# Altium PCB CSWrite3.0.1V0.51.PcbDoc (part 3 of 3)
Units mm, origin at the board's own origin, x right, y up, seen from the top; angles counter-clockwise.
Board outline 100 x 80 mm, 4 copper layers (Top Layer, power, gnd, Bottom Layer), stack 0.778 mm thick; 246 components, 181 nets, 873 pads, 864 vias.
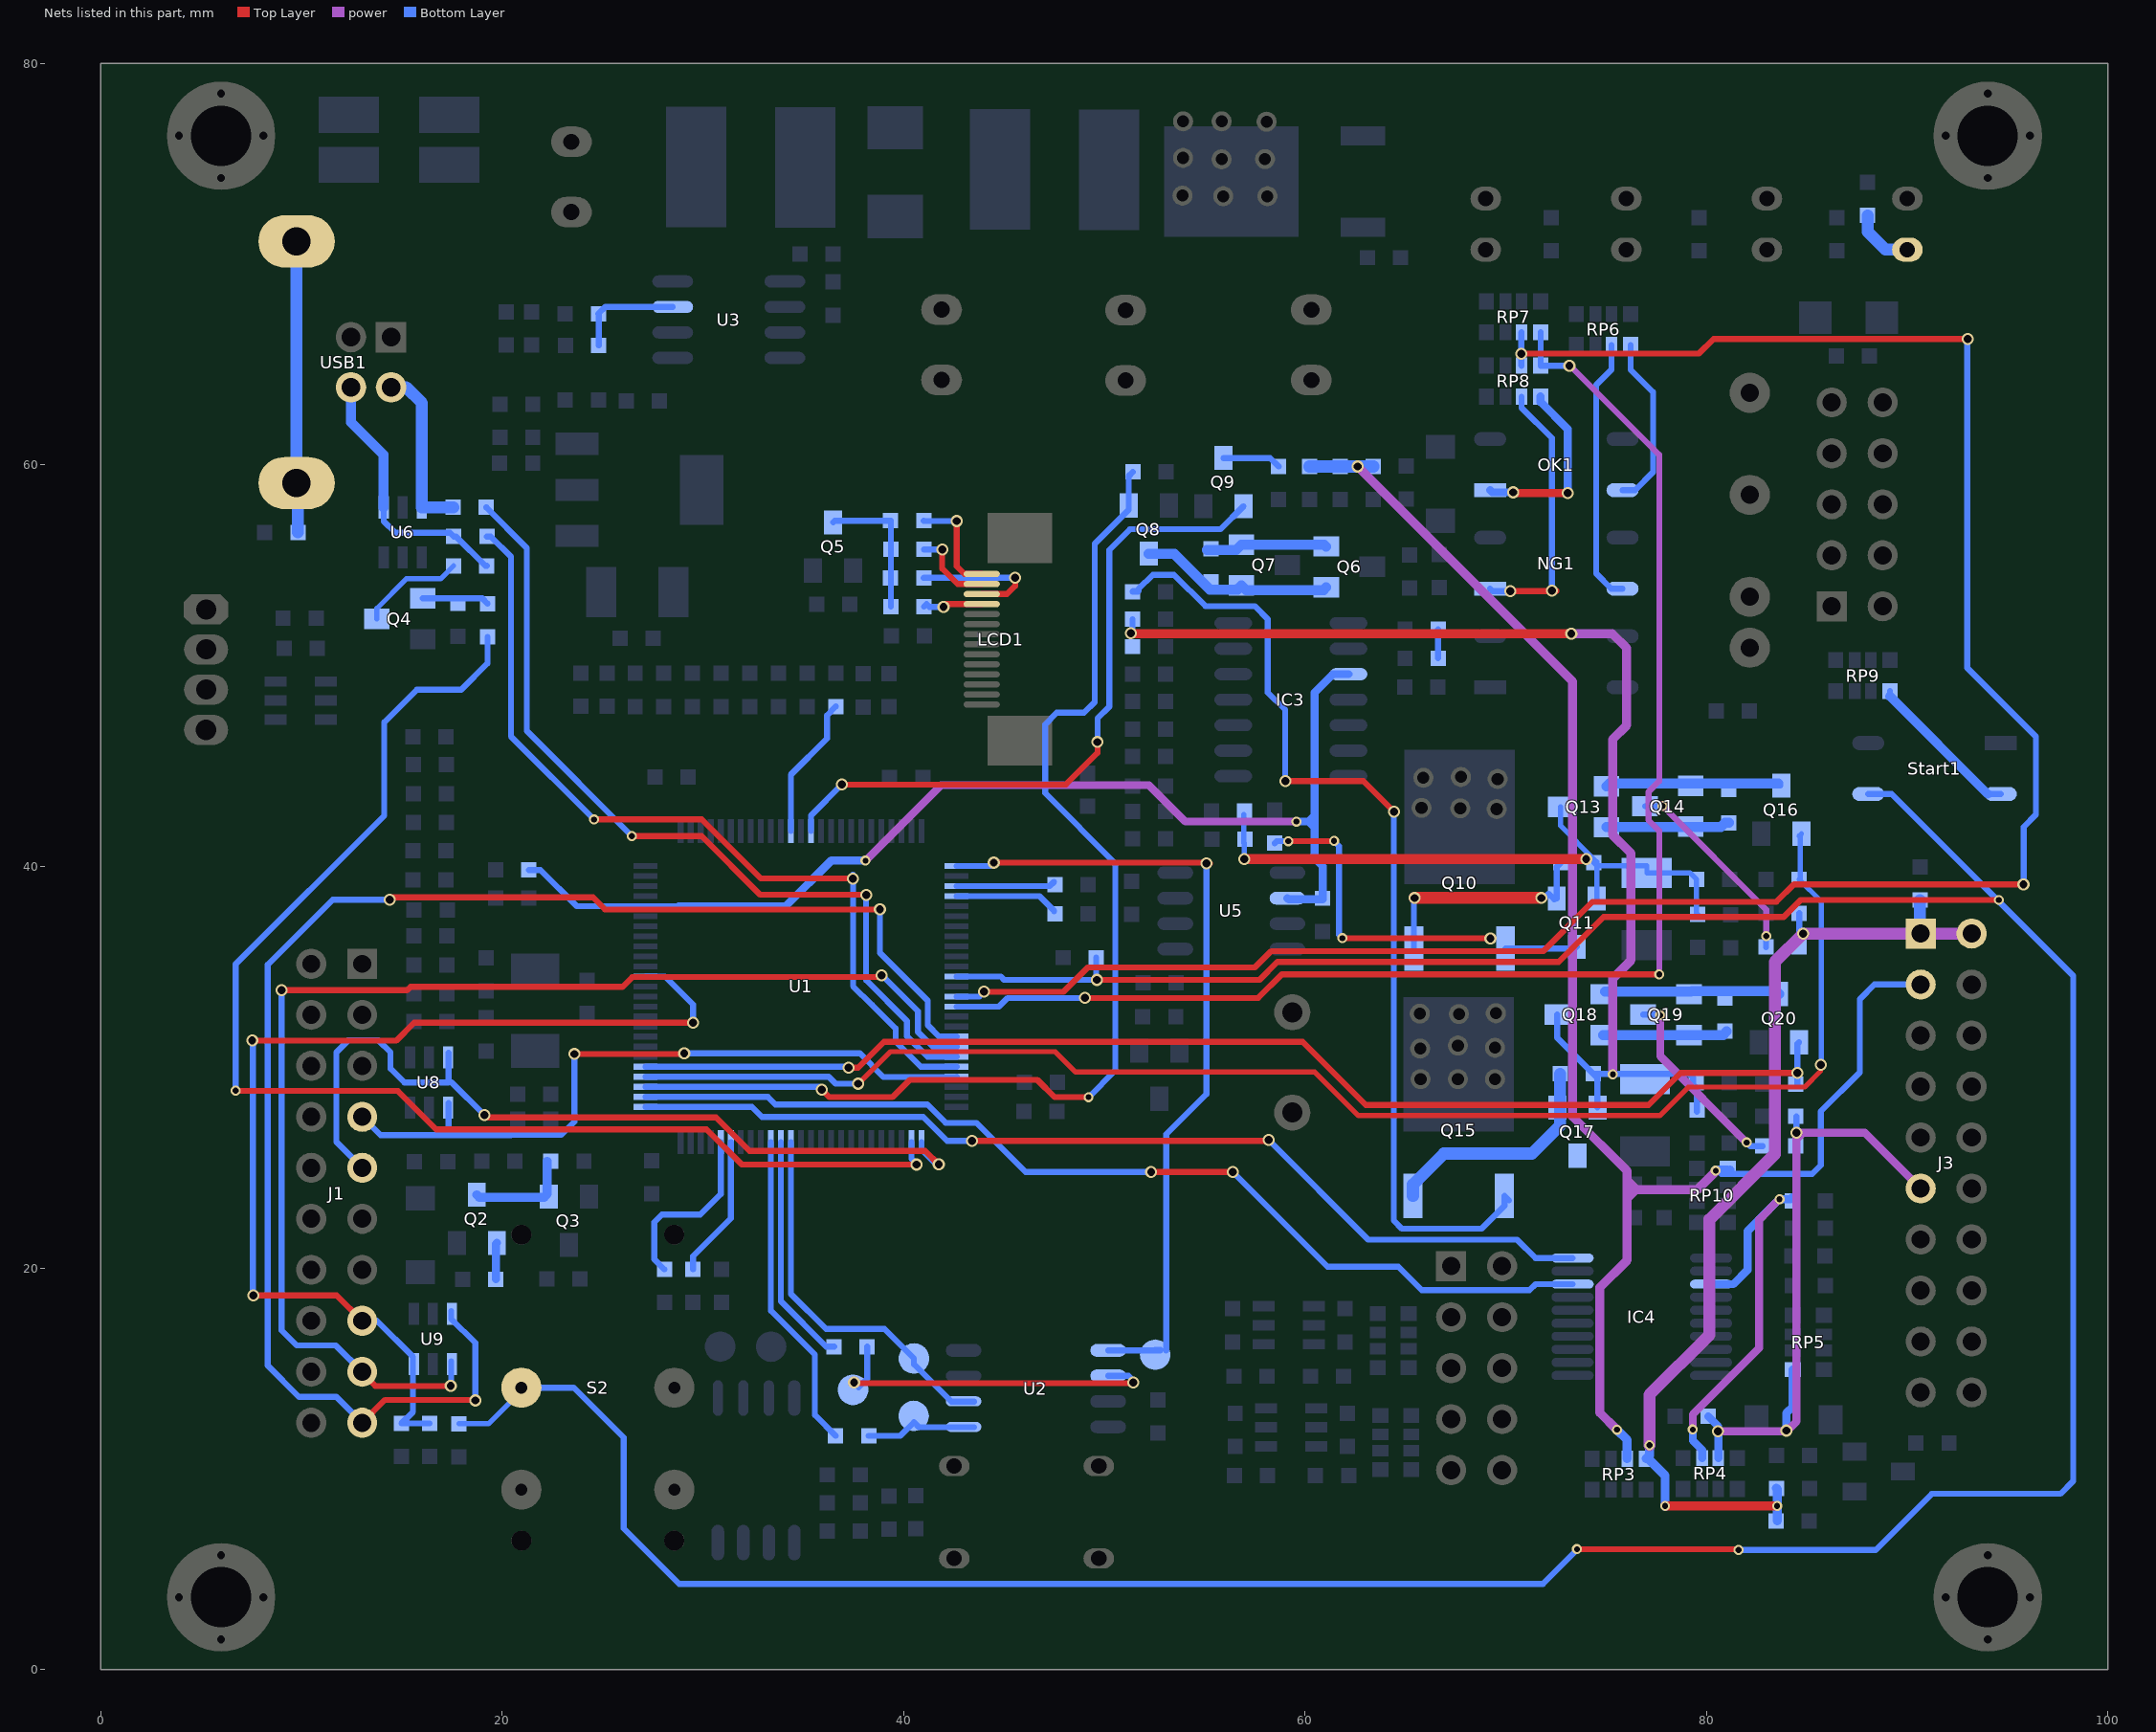
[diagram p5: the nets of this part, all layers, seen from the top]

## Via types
v1: diameter 0.5, hole 0.3, Top Layer to Bottom Layer, 444 vias
v2: diameter 0.6, hole 0.4, Top Layer to Bottom Layer, 412 vias
v3: diameter 0.8, hole 0.6, Top Layer to Bottom Layer, 8 vias

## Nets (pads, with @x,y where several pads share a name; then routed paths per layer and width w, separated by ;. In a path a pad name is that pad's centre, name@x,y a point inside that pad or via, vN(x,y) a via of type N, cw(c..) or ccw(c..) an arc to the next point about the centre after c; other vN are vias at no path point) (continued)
NetL9_1: L9.1 Q14.2 | length 10
  power w0.3: v1(77.81,43.01) 82.97,37.85 v1(82.97,36.53)
  Bottom Layer w0.3: Q14.2@76.928,43.003 77.803,43.003 v1(77.81,43.01) ; L9.1@82.959,35.991 82.959,36.519 v1(82.97,36.53)
NetL10_1: L10.1 Q19.2 | length 9.9
  power w0.4: v1(77.69,32.59) 77.69,30.55 v1(81.99,26.25)
  Bottom Layer w0.3: Q19.2@76.833,32.62 77.66,32.62 v1(77.69,32.59) ; v1(81.99,26.25) 82.17,26.07 L10.1@82.795,26.07
NetL11_2: L11.2 USB1.5 USB1.6 | length 14.5
  Bottom Layer w0.6: USB1.5@9.76,71.14 USB1.6@9.76,59.1 9.825,59.034 L11.2@9.825,56.64
NetLCD1_11: LCD1.11 R16.2 | length 3.1
  Top Layer w0.3: v2(41.99,52.93) 41.99,53.07 LCD1.11@43.89,53.07
  Bottom Layer w0.3: R16.2@41.014,52.945 41.139,53.07 41.279,52.93 v2(41.99,52.93)
NetLCD1_12: LCD1.12 R18.2 | length 6.8
  Top Layer w0.3: LCD1.12@43.89,53.57 45.15,53.57 45.56,53.98 v2(45.56,54.38)
  Bottom Layer w0.3: R18.2@41.004,54.375 41.009,54.38 v2(45.56,54.38)
NetLCD1_13: LCD1.13 R19.2 | length 4.2
  Top Layer w0.3: v2(41.92,55.8) 41.92,54.84 42.69,54.07 LCD1.13@43.89,54.07
  Bottom Layer w0.3: R19.2@41.014,55.795 41.915,55.795 v2(41.92,55.8)
NetLCD1_14: LCD1.14 R21.2 | length 5.3
  Top Layer w0.3: v2(42.65,57.21) 42.65,54.95 43.03,54.57 LCD1.14@43.89,54.57
  Bottom Layer w0.3: R21.2@41.004,57.225 41.019,57.21 v2(42.65,57.21)
NetNG1_1: NG1.1 RP8.6 | length 13.9
  Top Layer w0.3: v2(70.22,53.72) 72.51,53.72 72.52,53.73 72.51,53.74 v2(72.29,53.74)
  Bottom Layer w0.3: NG1.1@69.21,53.84 69.33,53.72 v2(70.22,53.72) ; RP8.6@70.78,63.41 70.78,62.85 72.29,61.34 v2(72.29,53.74)
NetNG1_4: NG1.4 RP6.6 | length 13.3
  Bottom Layer w0.3: RP6.6@75.26,65.98 75.26,64.75 74.5,63.99 74.5,54.59 75.25,53.84 NG1.4@75.81,53.84
NetOK1_1: OK1.1 RP8.5 | length 9.3
  Top Layer w0.4: v2(70.37,58.64) 70.39,58.66 70.45,58.6 v2(73.08,58.6)
  Bottom Layer w0.4: OK1.1@69.21,58.75 69.32,58.64 v2(70.37,58.64) ; RP8.5@71.73,63.41 71.73,63.14 73.08,61.79 v2(73.08,58.6)
NetOK1_4: OK1.4 RP6.5 | length 8.7
  Bottom Layer w0.3: OK1.4@75.81,58.75 76.44,58.75 77.33,59.64 77.33,63.626 76.21,64.746 RP6.5@76.21,65.98
NetPOWER_1: POWER.1 R12.1 | length 3.2
  Bottom Layer w0.6: R12.1@88.02,72.435 88.02,71.62 88.91,70.73 POWER.1@90,70.73
NetQ2_1: Q2.1 R4.1 | length 1.8
  Bottom Layer w0.4: R4.1@19.685,19.44 19.685,21.196 Q2.1@19.74,21.25
NetQ2_2: Q2.2 Q3.1 R10.2 | length 5.3
  Bottom Layer w0.45: Q2.2@18.74,23.65 18.866,23.524 19.449,23.524 22.092,23.524 22.219,23.651 22.252,23.683 R10.2@22.252,25.318
NetQ4_1: Q4.1 R11.2 R13.1 | length 3.3
  Bottom Layer w0.3: Q4.1@16.043,53.356 19.009,53.356 R13.1@19.27,53.095
NetQ4_2: Q4.2 R9.2 | length 5.2
  Bottom Layer w0.254: Q4.2@13.757,52.34 13.757,52.857 15.23,54.33 16.934,54.33 R9.2@17.584,54.98
NetQ5_2: Q5.2 R16.1 R18.1 R19.1 R21.1 | length 7.2
  Bottom Layer w0.3: Q5.2@36.488,57.145 36.568,57.225 R21.1@39.353,57.225 39.363,57.215 R16.1@39.363,52.945
NetQ6_1: Q6.1 Q7.1 Q8.2 R30.1 | length 9.8
  Bottom Layer w0.5: Q8.2@52.21,55.583 53.477,55.583 55.26,53.8 56.623,53.8 Q7.1@56.827,54.004 57.061,53.77 60.913,53.77 Q6.1@61.047,53.904
NetQ6_3: Q6.3 Q7.3 R30.2 | length 6.1
  Bottom Layer w0.5: R30.2@55.1,55.775 56.566,55.775 Q7.3@56.827,56.036 60.947,56.036 Q6.3@61.047,55.936
NetQ9_2: Q9.2 R34.2 | length 2.9
  Bottom Layer w0.3: Q9.2@55.93,60.35 58.256,60.35 R34.2@58.68,59.925
NetQ10_1: Q10.1 Q11.2 R42.2 | length 19
  Top Layer w0.3: v1(59.16,41.26) v1@61.44,41.26 ; v1(61.86,36.43) 69.1,36.43 69.14,36.39 69.2,36.45 v2(69.23,36.42)
  Bottom Layer w0.3: R42.2@58.48,41.16 58.58,41.26 v1(59.16,41.26) v1@59.251,41.26 ; v1@61.52,41.186 61.69,41.016 61.69,36.6 v1(61.86,36.43) ; Q10.1@69.98,35.915 73.443,35.915 Q11.2@73.53,36.003
  other v1: 61.44,41.27
NetQ10_3: Q10.3 Q11.1 R45.1 | length 11.6
  Top Layer w0.6: v2@65.45,38.44 v2@71.62,38.44
  Bottom Layer w0.3: Q10.3@65.42,35.915 65.42,38.4 v2(65.45,38.43) ; v2(71.76,38.43) 71.923,38.43 72.133,38.64 72.413,38.36 72.493,38.44 Q11.1@72.53,38.403 72.53,39.978 R45.1@72.735,40.183
NetQ13_1: Q13.1 Q14.1 Q16.2 R49.1 | length 8.7
  Bottom Layer w0.3: Q16.2@83.563,44.13 Q16.2@83.661,44.033
  Bottom Layer w0.5: Q13.1@75.013,43.989 75.155,44.13 Q16.2@83.563,44.13
NetQ13_3: Q13.3 Q14.3 R49.2 | length 6.2
  Bottom Layer w0.5: Q13.3@75.013,41.957 80.71,41.957 80.931,42.177 R49.2@81.11,42.177
NetQ15_1: Q15.1 Q17.2 R50.2 | length 50.2
  Top Layer w0.3: v2(59.01,44.25) 62.9,44.25 v2(64.42,42.73)
  Bottom Layer w0.3: v2(59.01,44.25) 59.01,47.8 58.14,48.67 58.14,52.322 57.492,52.97 55.03,52.97 53.47,54.53 52.41,54.53 51.71,53.83 R50.2@51.71,53.73 ; v2(64.42,42.73) 64.42,22.359 64.819,21.96 68.79,21.96 69.93,23.1 Q15.1@69.93,23.59 Q15.1@70.16,23.36 ; R50.2@51.71,53.73 51.67,53.69 R50.2@51.401,53.69 51.441,53.73 R50.2@51.71,53.73
NetQ15_3: Q15.3 Q17.1 R55.1 | length 11.7
  Bottom Layer w0.6: Q15.3@65.37,23.59 65.37,24.16 66.91,25.7 71.3,25.7 72.705,27.105 R55.1@72.705,29.67
NetQ18_1: Q18.1 Q19.1 Q20.2 R58.1 | length 8.7
  Bottom Layer w0.5: Q18.1@74.933,33.776 79.209,33.776 79.273,33.79 83.461,33.79 Q20.2@83.606,33.645
NetQ18_3: Q18.3 Q19.3 R58.2 | length 6.2
  Bottom Layer w0.5: Q18.3@74.843,31.604 Q19.3@79.119,31.604 80.82,31.604 R58.2@80.996,31.779
NetR6_2: R6.2 R9.1 U6.4 USB1.3 | length 13.4
  Bottom Layer w0.3: U6.4@14.1,57.89 14.1,57.2 14.68,56.62 17.406,56.62 R6.2@17.588,56.438 17.702,56.438 19.16,54.98 R9.1@19.235,54.98
  Bottom Layer w0.5: USB1.3@12.47,63.87 12.47,62.14 14.1,60.51 U6.4@14.1,57.89
NetR7_2: R7.2 U6.6 USB1.2 | length 7.9
  Bottom Layer w0.6: USB1.2@15.22,63.87 16,63.09 U6.6@16,57.89 17.55,57.89 R7.2@17.558,57.898
NetR20_2: R20.2 R23.1 U3.3 | length 5.4
  Bottom Layer w0.3: R23.1@24.813,65.953 24.813,67.513 R20.2@24.793,67.533 25.135,67.875 U3.3@28.496,67.875
NetR28_2: R28.2 R29.2 | length 1.4
  Bottom Layer w0.3: R29.2@66.627,50.374 R28.2@66.627,51.814
NetR54_2: R54.2 U1.54 | length 5.2
  Bottom Layer w0.3: U1.54@42.637,38.522 46.768,38.522 47.495,37.795 R54.2@47.495,37.775
NetR57_2: R57.2 U1.95 | length 7.1
  Bottom Layer w0.3: R57.2@29.506,19.927 29.506,20.586 31.387,22.467 U1.95@31.387,26.272
NetR62_2: R62.2 U1.96 | length 9
  Bottom Layer w0.3: R62.2@28.086,19.927 27.58,20.433 27.58,22.275 27.965,22.66 29.87,22.66 30.887,23.677 U1.96@30.887,26.272
NetR65_2: R65.2 U1.53 | length 4.9
  Bottom Layer w0.3: U1.53@42.637,39.022 47.277,39.022 R65.2@47.495,39.24
NetR68_2: R68.2 U1.37 | length 7.1
  Bottom Layer w0.3: U1.37@34.387,41.772 34.387,44.577 36.18,46.37 36.18,47.528 R68.2@36.621,47.969
NetR72_2: R72.2 U1.90 | length 11.5
  Bottom Layer w0.3: U1.90@33.887,26.272 33.887,18.333 36.138,16.082 R72.2@36.535,16.082
NetR73_2: R73.2 U1.91 | length 16
  Bottom Layer w0.3: U1.91@33.387,26.272 33.387,17.873 35.58,15.68 35.58,12.666 R73.2@36.61,11.637
NetRP9_1: RP9.1 Start1.2 | length 7.8
  Bottom Layer w0.3: RP9.1@89.13,48.48 RP9.1@89.13,48.74 ; Start1.2@94,43.61 Start1.2@94.65,43.61
  Bottom Layer w0.45: RP9.1@89.13,48.48 Start1.2@94,43.61
NG: RP7.2 RP8.3 U1.64 | length 108.5
  Top Layer w0.3: v2(44.01,33.76) 47.97,33.76 49.18,34.97 57.5,34.97 58.31,35.78 71.86,35.78 74.32,38.24 83.47,38.24 84.34,39.11 v2(95.78,39.11) ; v2(70.77,65.53) 70.79,65.55 79.62,65.55 80.35,66.28 v2(93.01,66.28)
  Bottom Layer w0.3: U1.64@42.637,33.522 43.772,33.522 v2(44.01,33.76) ; RP8.3@70.78,64.95 70.77,64.96 v2(70.77,65.53) 70.77,66.6 RP7.2@70.78,66.61 ; v2@93.01,66.17 92.98,66.14 92.98,49.89 96.4,46.47 96.4,42.58 95.79,41.97 v2@95.79,39.11 ; v2@93.01,66.17 v2(93.01,66.28)
OE: IC4.10 U1.1 | length 49.3
  Top Layer w0.3: v2(43.41,26.33) 58.14,26.33 v2(58.18,26.37)
  Bottom Layer w0.3: U1.1@27.137,28.022 32.438,28.022 32.94,27.52 40.98,27.52 42.17,26.33 v2(43.41,26.33) ; v2(58.18,26.37) 63.14,21.41 70.56,21.41 71.475,20.495 IC4.10@73.32,20.495
OK: RP7.1 RP8.4 U1.65 | length 71.4
  Top Layer w0.3: v2(49.03,33.45) 57.66,33.45 58.84,34.63 v1(77.64,34.63)
  power w0.3: v2(73.165,64.95) 73.2,64.95 77.64,60.51 77.64,44.25 77.11,43.72 77.11,42.31 77.64,41.78 v1(77.64,34.63)
  Bottom Layer w0.3: U1.65@42.637,33.022 44.752,33.022 45.18,33.45 v2(49.03,33.45) ; RP7.1@71.73,66.61 RP8.4@71.73,64.95 72.36,64.95 v2(73.165,64.95)
Rest: C2.2 J1.15 R66.1 U1.14 U9.6 | length 53.1
  Top Layer w0.3: v2(7.55,31.34) 7.55,31.32 14.72,31.32 15.62,32.22 v2(29.51,32.22) ; v2(7.6,18.64) 11.76,18.64 J1.15@13.03,17.37
  Bottom Layer w0.3: v2@7.59,31.34 7.59,18.64 v2(7.6,18.64) ; J1.15@13.03,17.37 13.76,17.37 15.56,15.57 15.56,12.829 C2.2@14.986,12.255 R66.1@16.383,12.255 ; U1.14@27.137,34.522 28.108,34.522 29.51,33.12 v2(29.51,32.22)
Rest-a: IC4.8 U1.2 | length 50.4
  Top Layer w0.3: v2@52.219,24.78 v2(52.33,24.78) v2(56.4,24.78)
  Bottom Layer w0.3: U1.2@27.137,28.522 33.238,28.522 33.61,28.15 41.18,28.15 42.1,27.23 43.62,27.23 46.07,24.78 v2(52.33,24.78) ; v2(56.4,24.78) 61.115,20.065 64.645,20.065 65.81,18.9 71.18,18.9 71.475,19.195 IC4.8@73.32,19.195
Rest-b: IC4.13 R41.1 RP4.6 | length 21.9
  power w0.4: v1(79.31,11.95) 79.31,12.706 82.618,16.014 82.618,22.418 v1(83.63,23.43)
  Bottom Layer w0.4: v1(79.31,11.95) 79.31,11.4 79.78,10.93 RP4.6@79.78,10.53 ; IC4.13@80.22,19.195 81.335,19.195 82.04,19.9 82.04,21.84 v1(83.63,23.43) ; v1@83.63,23.444 v1(83.63,23.43) ; R41.1@84.271,23.522 84.179,23.43 v1(83.63,23.43)
Rx: J1.17 U1.69 U9.4 | length 63.6
  Top Layer w0.3: v2(9.02,33.84) 15.27,33.84 15.44,34.01 26,34.01 26.48,34.49 38.81,34.49 v2(38.9,34.58) ; J1.17@13.03,14.83 13.47,14.39 13.44,14.36 13.68,14.12 v2(17.44,14.12)
  Bottom Layer w0.3: v2(9.02,33.84) 9.02,16.888 9.768,16.14 11.72,16.14 J1.17@13.03,14.83 ; v2@17.46,14.36 U9.4@17.46,15.345 ; v2(38.9,34.58) 38.92,34.58 40.715,32.785 40.715,31.755 41.448,31.022 U1.69@42.637,31.022
SPI2-CLK: T9.1 U1.89 U2.6 | length 19.1
  Bottom Layer w0.3: U1.89@34.387,26.272 34.387,18.703 36.13,16.96 39.047,16.96 T9.1@40.513,15.494 40.513,15.207 42.385,13.335 U2.6@43.517,13.335
SPI2-CS: T7.1 U1.51 U2.1 | length 40.9
  Top Layer w0.3: v2(44.49,40.19) 54.97,40.19 55.08,40.3 v2@55.23,40.15 ; v2(55.08,40.15) v2@55.23,40.15 ; v2@55.23,40.15 55.25,40.15 55.24,40.14 v2@55.23,40.15
  Bottom Layer w0.3: U1.51@42.637,40.022 44.322,40.022 v2(44.49,40.19) ; U2.1@50.187,15.895 T7.1@52.783,15.895 ; T7.1@52.54,15.912 T7.1@52.8,15.912 ; T7.1@53.07,15.892 53.08,15.902 53.08,26.66 55.08,28.66 v2(55.08,40.15)
SPI2-MISO: R72.1 T8.1 U2.2 | length 17.6
  Top Layer w0.3: v2(37.53,14.29) 37.56,14.26 51.4,14.26 v2(51.44,14.3)
  Bottom Layer w0.3: T8.1@37.757,14.063 38.186,14.492 R72.1@38.186,16.082 ; U2.2@50.187,14.625 51.195,14.625 51.44,14.38 v2(51.44,14.3)
SPI2-MOSI: R73.1 T10.1 U2.5 | length 5.6
  Bottom Layer w0.3: R73.1@38.261,11.637 39.831,11.637 40.513,12.319 40.767,12.065 U2.5@43.517,12.065
Start: C39.1 R67.1 S2.2 Start1.3 U1.62 | length 184.3
  Top Layer w0.254: S2.2@20.96,14.35 21.14,14.17 S2.2@21.15,14.18
  Top Layer w0.3: v2(49.63,34.35) 57.73,34.35 58.62,35.24 72.63,35.24 74.87,37.48 83.84,37.48 84.692,38.332 v1(94.55,38.332) ; v1(73.54,5.99) 81.558,5.99 v1(81.588,5.96)
  Bottom Layer w0.254: R67.1@17.855,12.242 19.319,12.242 20.96,13.883 S2.2@20.96,14.04
  Bottom Layer w0.3: S2.2@20.96,14.04 23.567,14.04 26.05,11.557 26.05,7.025 28.815,4.26 71.85,4.26 73.54,5.95 v1(73.54,5.99) ; U1.62@42.637,34.522 44.838,34.522 45.01,34.35 v2(49.63,34.35) 49.63,34.4 49.59,34.44 C39.1@49.59,35.46 ; v1(81.588,5.96) 88.42,5.96 91.21,8.75 97.62,8.75 98.26,9.39 98.26,34.56 89.21,43.61 Start1.3@88.05,43.61
SWCLK: J1.9 U1.76 U8.3 | length 42.6
  Top Layer w0.3: v2(19.11,27.62) 19.23,27.5 30.66,27.5 32.33,25.83 41.07,25.83 41.75,25.15 v2(41.75,25.16)
  Bottom Layer w0.3: J1.9@13.03,24.99 11.74,26.28 11.74,30.74 12.35,31.35 13.83,31.35 14.44,30.74 14.44,29.93 15.13,29.24 17.323,29.24 17.333,29.25 ; U8.3@17.333,30.714 17.333,29.25 ; v2(19.11,27.62) 17.48,29.25 17.333,29.25 ; U1.76@40.887,26.272 40.887,25.913 41.63,25.17 41.67,25.21 41.72,25.16 v2(41.75,25.16)
SWDIO: J1.7 U1.72 U8.4 | length 35.7
  Top Layer w0.3: v2(23.6,30.66) 29.03,30.66 v2(29.07,30.7)
  Bottom Layer w0.3: J1.7@13.03,27.53 13.94,26.62 17.333,26.62 ; U8.4@17.333,28.214 17.333,26.62 ; v2(23.6,30.66) 23.6,27.29 22.94,26.63 20.45,26.63 20.44,26.62 17.333,26.62 ; v2(29.07,30.7) 37.79,30.7 37.8,30.71 39,29.51 42.625,29.51 U1.72@42.637,29.522
Tx: J1.19 U1.68 U9.3 | length 77.5
  Top Layer w0.3: J1.19@13.03,12.29 14.17,13.43 18.63,13.43 v2(18.66,13.4) ; v2(14.405,38.35) 14.405,38.46 24.53,38.46 25.13,37.86 v2(38.82,37.86)
  Bottom Layer w0.3: J1.19@13.03,12.29 11.74,13.58 9.88,13.58 8.32,15.14 8.32,35.11 11.56,38.35 v2(14.405,38.35) ; U9.3@17.46,17.845 17.46,17.47 18.66,16.27 v2(18.66,13.4) ; v2(38.82,37.86) 38.82,35.69 41.2,33.31 41.2,32.09 41.768,31.522 U1.68@42.637,31.522
USBDM: R7.1 U1.70 | length 43.1
  Top Layer w0.3: v1(26.46,41.508) 29.942,41.508 32.86,38.59 v2(38.13,38.59)
  Bottom Layer w0.3: R7.1@19.209,57.898 19.209,57.881 21.23,55.86 21.23,46.75 26.46,41.52 v1(26.46,41.508) ; v2(38.13,38.59) 38.13,34.34 40.17,32.3 40.17,31.54 41.188,30.522 U1.70@42.637,30.522
USBDP: R6.1 U1.71 | length 43.5
  Top Layer w0.3: v1(24.58,42.34) 24.59,42.35 29.94,42.35 32.89,39.4 v2(37.47,39.4)
  Bottom Layer w0.3: R6.1@19.239,56.438 19.432,56.438 20.44,55.43 20.44,46.48 v1(24.58,42.34) ; v2(37.47,39.4) 37.47,39.59 37.48,39.6 37.48,34.038 38.418,33.1 38.428,33.11 39.6,31.938 39.6,31.28 40.858,30.022 U1.71@42.637,30.022
USBEN: R13.2 U1.77 | length 65.8
  Top Layer w0.3: v1@6.73,28.82 14.8,28.82 16.71,26.91 30.18,26.91 31.94,25.15 v2(40.65,25.15)
  Bottom Layer w0.3: v1(6.73,28.83) 6.73,35.14 14.13,42.54 14.13,47.19 15.75,48.81 17.961,48.81 19.27,50.119 R13.2@19.27,51.444 ; U1.77@40.387,26.272 40.387,25.443 40.65,25.18 v2(40.65,25.15)
Vdd: C30.1 C31.2 C50.2 Q11.3 Q13.2 R45.2 R46.2 R47.1 | length 32.6
  Top Layer w0.5: v2(56.964,40.376) v2@74,40.376
  Bottom Layer w0.254: C31.2@56.944,42.586 56.944,41.186 56.964,41.166 v2(56.964,40.376) ; Q13.2@72.727,42.973 72.727,42.023 R45.2@74.388,40.362 ; v2(74,40.362) R45.2@74.388,40.362 ; R45.2@74.386,40.183 R45.2@74.388,40.181 ; Q11.3@74.53,38.403 R45.2@74.53,40.038 ; C50.2@79.56,37.616 79.495,37.681 R47.1@79.494,39.36 79.172,39.683 C30.1@77.02,39.683 77.02,40.038 R45.2@74.53,40.038 ; R45.2@74.388,40.181 R45.2@74.53,40.038 ; R45.2@74.388,40.181 R45.2@74.388,40.362 ; R45.2@74.388,40.362 74.53,40.22 R45.2@74.53,40.038
Vdd-b: C33.2 C76.1 J3.1 J3.2 L9.2 R37.1 R75.1 RP3.8 | length 51
  Top Layer w0.45: v1(77.93,8.14) v1(83.51,8.14)
  power w0.6: v1(77.15,11.17) 77.15,13.68 80.14,16.67 80.14,22.41 83.4,25.67 83.4,35.25 v2(84.81,36.66) J3.1@90.66,36.66 J3.2@93.2,36.66
  Bottom Layer w0.3: v2@84.61,36.66 C33.2@84.61,37.675
  Bottom Layer w0.45: v1(77.15,11.17) 77.15,10.66 RP3.8@76.99,10.5 77.09,10.5 77.93,9.66 v1(77.93,8.14) ; R37.1@83.474,9.02 83.51,8.984 v1(83.51,8.14) R75.1@83.51,7.4 ; J3.2@93.2,36.66 J3.2@93.7,36.66
  Bottom Layer w0.6: C76.1@90.628,38.325 90.628,36.692 J3.1@90.66,36.66
VddOn: Q16.1 R53.2 U1.4 | length 74
  Top Layer w0.254: v2(37.74,29.18) 39.34,30.78 47.55,30.78 48.57,29.76 60.48,29.76 62.65,27.59 77.67,27.59 79.09,29.01 84.88,29.01 85.68,29.81 v2(85.68,30.12) v2@85.67,30.12
  Bottom Layer w0.254: Q16.1@84.72,41.63 84.61,41.52 84.67,41.459 84.67,39.42 R53.2@84.61,39.36 85.71,38.26 v2@85.71,30.12
  Bottom Layer w0.3: U1.4@27.137,29.522 36.268,29.522 36.61,29.18 v2(37.74,29.18)
Vpp: C36.1 C37.2 C51.2 Q17.3 Q18.2 R55.2 R56.2 R60.1 | length 60.4
  Top Layer w0.3: v2(51.31,51.62) v2@51.35,51.58
  Top Layer w0.45: v2@51.35,51.58 51.37,51.6 v2(73.26,51.6)
  power w0.45: v2(73.26,51.6) 75.3,51.6 76.02,50.88 76.02,47.035 75.31,46.325 75.31,41.58 76.233,40.657 76.233,35.333 75.33,34.43 v1(75.33,29.64)
  Bottom Layer w0.3: v2@51.401,51.56 R56.2@51.401,52.321 ; Q18.2@72.557,32.62 72.557,31.469 R55.2@74.356,29.67 ; Q17.3@74.564,27.995 74.564,29.462 R55.2@74.356,29.67 ; C51.2@79.52,27.785 79.52,28.945 79.325,29.14 79.325,29.485 79.14,29.67 R55.2@74.356,29.67
Vpp-b: C38.2 C77.1 J3.11 L10.2 RP4.7 RP5.5 | length 33.3
  power w0.4: v2(80.572,11.868) 83.938,11.868 v2(83.97,11.9) 84.02,11.9 84.476,12.356 84.476,26.406 ; J3.11@90.66,23.96 87.89,26.73 84.8,26.73 ; 84.476,26.406 84.8,26.73 ; 84.476,26.406 v2(84.476,26.73) 84.8,26.73
  Bottom Layer w0.3: L10.2@84.476,25.97 v2(84.476,26.73) C38.2@84.476,27.545
  Bottom Layer w0.4: C77.1@80.076,12.61 80.572,12.114 v2(80.572,11.868) 80.58,11.86 RP4.7@80.58,10.53 ; v2(83.97,11.9) 83.97,12.77 84.29,13.09 84.29,14.936 RP5.5@84.296,14.942
VppOn: Q20.1 R64.2 U1.5 | length 62.1
  Top Layer w0.3: v2(37.26,29.98) 37.74,29.98 39.02,31.26 59.88,31.26 63.02,28.12 77.104,28.12 78.704,29.72 v2(84.526,29.72)
  Bottom Layer w0.3: U1.5@27.137,30.022 37.218,30.022 v2(37.26,29.98) ; R64.2@84.526,29.12 v2(84.526,29.72) 84.526,31.164 Q20.1@84.606,31.245
VREF: C17.2 C49.2 IC3.10 U1.21 U5.6 | length 58.3
  power w0.4: v1(38.1,40.29) 41.86,44.05 52.22,44.05 54.03,42.24 v1(59.56,42.24)
  Bottom Layer w0.3: C49.2@21.331,39.829 21.911,39.829 23.718,38.022 U1.21@27.137,38.022 28.788,38.022
  Bottom Layer w0.4: 28.788,38.022 34.122,38.022 36.4,40.3 v1@38.1,40.3 ; U5.6@59.12,38.422 59.179,38.362 60.881,38.362 60.881,39.999 60.48,40.4 60.48,41.93 ; v1(59.56,42.24) 60.17,42.24 ; IC3.10@62.16,49.58 61.39,49.58 60.48,48.67 60.48,42.55 ; 60.17,42.24 60.48,42.55 ; 60.17,42.24 60.48,42.24 ; 60.17,42.24 60.48,41.93 ; 60.48,41.93 60.48,42.24 ; 60.48,42.24 60.48,42.55
VS-b: C16.1 J3.3 L8.2 R31.1 RP3.7 RP10.5 | length 84.6
  power w0.45: v2(62.61,59.925) 62.615,59.925 73.32,49.22 73.32,27.55 76.04,24.83 76.04,24.32 ; v1(75.53,11.943) 74.677,12.796 74.677,19.027 76.04,20.39 76.04,23.47 ; v1(80.455,24.845) 80.455,24.815 79.55,23.91 76.48,23.91 ; 76.04,23.47 76.04,23.91 ; 76.04,23.47 76.48,23.91 ; 76.04,23.91 76.48,23.91 ; 76.04,23.91 76.04,24.32 ; 76.04,24.32 76.07,24.32 76.48,23.91
  Bottom Layer w0.3: RP10.5@81.05,24.965 80.574,24.965 v1(80.455,24.845) v1@80.575,24.845 ; RP10.5@81.17,24.96 81.23,24.9 81.175,24.845 v1@80.575,24.845 ; J3.3@90.66,34.12 88.36,34.12 87.63,33.39 87.63,29.74 85.69,27.8 85.69,25.12 85.26,24.69 80.73,24.69 v1@80.575,24.845
  Bottom Layer w0.45: v1(75.53,11.943) 76.04,11.433 RP3.7@76.04,10.5
  Bottom Layer w0.6: R31.1@60.217,59.925 v2(62.61,59.925) C16.1@63.4,59.925
VSOn: Q8.1 R36.2 U1.3 | length 58.8
  Top Layer w0.3: v2(35.93,28.88) 36.3,28.51 39.44,28.51 40.3,29.37 46.66,29.37 47.52,28.51 v1(49.21,28.51)
  Bottom Layer w0.3: U1.3@27.137,29.022 35.788,29.022 v2(35.93,28.88) ; v1(49.21,28.51) 49.22,28.51 50.54,29.83 50.54,40.16 47.046,43.654 47.046,47.076 47.627,47.657 48.987,47.657 49.52,48.19 49.52,56.07 51.21,57.76 Q8.1@51.21,57.983 51.21,59.448 R36.2@51.415,59.653
VSOn-b: Q9.1 U1.39 | length 34.3
  Top Layer w0.3: v2(36.93,44.08) 48.08,44.08 49.66,45.66 v2(49.66,46.2)
  Bottom Layer w0.3: U1.39@35.387,41.772 35.387,42.537 v2(36.93,44.08) ; v2(49.66,46.2) 49.66,47.38 50.24,47.96 50.24,55.77 51.27,56.8 55.78,56.8 Q9.1@56.93,57.95
pads on no net: IC3.12 IC3.13 IC3.14 IC4.9 IC4.12 J1.2 J1.11 LCD1.0 RP4.4 RP4.5 RP6.8 RP7.4 RP7.5 RP8.1 RP8.8 S2.0 S2.3 S2.4 U1.9 U1.40 U1.41 U1.42 U1.43 U1.44 U1.45 U1.46 U1.57 U1.85 U1.97 U3.4 U5.1 U5.3 U5.5 U5.7 U5.8 U6.1 U6.3 U6.5 U7.5 U8.5 U9.5 U10.1 U10.3 U10.5 U11.5

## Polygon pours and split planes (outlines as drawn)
12V on power "Top Layer-No Net" (solid, remove dead copper, pour order 2): 63.61,27.41 64.24,26.78 70.72,26.78 71.2,27.26 71.2,47.03 70.62,47.61 64.16,47.61 63.61,47.06
3.3V on power "Top Layer-No Net" (solid, remove dead copper, pour order 0): 16.74,9.59 14.45,11.89 14.45,32.99 13.55,33.89 12.26,33.89 12.26,41.25 16.01,45 16.01,52.32 17.27,53.58 21.28,53.58 22.06,52.8 34.06,52.8 35.46,54.2 39.68,54.2 41.53,52.35 42.19,52.35 42.39,52.15 42.39,51.88 41.98,51.47 40.54,51.47 39.54,52.47 38.28,52.47 37.81,52 37.81,49.94 40.5,47.25 40.5,46.66 40.35,46.51 39.69,46.51 38,48.2 30.64,48.2 30.02,47.58 30.02,44.49 29.88,44.35 29.65,44.35 29.49,44.51 29.49,45.74 28.35,46.88 27.02,46.88 26.63,46.49 26.63,40.25 28.64,38.24 28.64,36.32 26.53,34.21 26.53,29.1 27.83,27.8 27.83,25.88 24.83,22.88 24.83,20.37 22.77,18.31 18.21,18.31 17.5,17.6 17.5,13.54 18.26,12.78 18.26,9.94 17.78,9.46 16.87,9.46
GND on power "Top Layer-No Net" (solid, remove dead copper, pour order 12): 100,80 100,0 0,0 0,80
GND on gnd "Top Layer-No Net" (solid, remove dead copper, pour order 6): 100,80 100,0 0,0 0,80
GND on Bottom Layer "Top Layer-No Net" (solid, remove dead copper, pour order 8): 100,80 100,0 0,0 0,80
GND on Top Layer "Top Layer-No Net" (solid, remove dead copper, pour order 10): 100,80 100,0 0,0 0,80

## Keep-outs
Keep-Out Layer:
  lines w0.15: 0,0 100,0 ; 0,0 0,80 ; 0,0 100,0 ; 0,0 0,80 ; 0,80 100,80 ; 0,80 100,80 ; 100,0 100,80 ; 100,0 100,80

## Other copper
Top Layer:
  rectangle net 12V: 63.49,28.63 73.76,33.62
  rectangle net 12V: 64.91,42.15 75.71,46.55
  rectangle net GND: 52.89,72.7 58.77,77.96
  region net AGND: 19.69,49.09 22.82,49.09 23.025,48.885 23.025,48.43 22.855,48.26 19.655,48.26 19.445,48.47 19.445,48.845
  region net AGND: 23.11,38.05 23.27,37.89 23.27,37.55 23.14,37.42 16.89,37.42 16.17,36.7 15.28,36.7 15.03,36.95 15.03,37.54 15.54,38.05
  pour cut-out: 80.24,60.88 80.24,57.27 81.04,56.47 83.03,56.47 83.95,55.55 83.95,49.29 85.3,47.94 91.56,47.94 92.41,48.79 92.41,67.24 91.241,68.409 82.909,68.409 80.24,65.74
  region net GND1: 77.33,19.602 79.622,17.31 86.94,17.31 87.04,17.41 87.04,17.88 86.98,17.94 80.01,17.94 77.85,20.1 77.5,20.1 77.33,19.93
power:
  pour cut-out: 80.24,60.88 80.24,57.27 81.04,56.47 83.35,56.47 84.08,55.74 84.08,49.102 85.222,47.96 91.6,47.96 92.35,48.71 92.35,66.78 92.27,66.86 81.44,66.86 80.24,65.66
  region net 5V-b: 81.6,62.37 83.28,62.38 86.03,65.13 91.86,65.13 92.03,65.3 92.03,66.35 91.87,66.51 81.75,66.51 80.81,65.57 80.81,62.6 81.04,62.37
gnd:
  pour cut-out: 80.24,60.88 80.24,57.27 81.04,56.47 83.35,56.47 84.08,55.74 84.08,49.125 85.264,47.94 91.56,47.94 92.35,48.73 92.35,67.25 91.15,68.45 81.57,68.45 80.24,67.12
Bottom Layer:
  rectangle net GND: 52.96,76.04 59.68,78.15
  rectangle net 12V: 66.42,32.95 68.53,40.64
  region net NetJ3_15: 86.45,23.33 86.27,23.15 85.92,23.15 85.82,23.25 85.948,23.378 85.948,24.198 86.08,24.33 86.34,24.33 86.45,24.22
  region net 3.3V: 28.82,26.87 27.479,26.87 27.08,26.471 27.08,25.015 27.09,25.005 28.416,25.005 28.82,25.409
  pour cut-out: 63.869,18.396 64.949,18.398 64.949,17.972 64.969,17.952 63.999,17.952 63.859,18.092 63.859,18.386
  pour cut-out: 85.49,18.624 86.57,18.626 86.57,18.2 86.59,18.18 85.62,18.18 85.48,18.32 85.48,18.614
  region net AGND: 15.21,45.46 15.2,45.47 15.64,45.47 16.82,46.65 16.82,46.88 19.191,49.251 19.906,49.251 20.05,49.106 20.05,48.31 17.87,46.13 17.13,46.13 15.98,44.98 15.98,33.35 15.86,33.23 15.29,33.23 15.21,33.31
  pour cut-out: 36.448,8.076 37.528,8.078 37.528,7.652 37.548,7.632 36.578,7.632 36.438,7.772 36.438,8.066
  pour cut-out: 22.485,19.249 23.564,19.251 23.564,18.825 23.584,18.805 22.614,18.805 22.474,18.945 22.474,19.239
  pour cut-out: 63.958,9.73 65.038,9.732 65.038,9.306 65.058,9.286 64.088,9.286 63.948,9.426 63.948,9.72
  pour cut-out: 58.828,60.59 59.908,60.592 59.908,60.166 59.928,60.146 58.958,60.146 58.818,60.286 58.818,60.58
  region net 12V: 61.76,72.17 61.76,70.94 59.22,68.4 59.22,66.776 59.536,66.46 61.11,66.46 61.67,65.9 61.67,63.529 60.821,62.68 51.026,62.68 47.242,58.896 47.242,51.34 47.85,50.732 47.85,48.17 48.75,48.17 48.88,48.3 48.88,56.27 50.42,57.81 50.42,60.049 52.031,61.66 61.88,61.66 63.099,62.879 63.099,66.131 61.16,68.07 62.64,68.07 63.99,69.42 63.99,72.53 63.98,72.54 61.837,72.54 61.747,72.45 61.747,72.173 61.77,72.15
  pour cut-out: 56.697,40.498 55.618,40.495 55.618,40.921 55.598,40.941 56.568,40.941 56.708,40.801 56.708,40.508
  pour cut-out: 58.447,42.388 57.368,42.385 57.368,42.811 57.348,42.831 58.318,42.831 58.458,42.691 58.458,42.398
  region net 3.3V: 26.79,56.73 25.97,57.55 22.882,57.55 22.626,57.806 22.626,59.71 23.139,60.223 26.416,60.223 27.323,61.13 33.62,61.13 34.66,60.09 34.66,51.37 30.35,51.37 29.98,51 26.94,51 26.79,51.15
  region net NetOK1_1: 68.402,59.106 70.485,59.106 70.637,58.953 70.637,58.471 70.536,58.369 68.428,58.369 68.402,58.395
  region net IO1-a: 72.28,14.55 73.435,13.395 74.37,14.33 74.37,14.66 74.34,14.69 72.32,14.69 72.28,14.65
  region net D4: 63.91,13.27 64.15,13.03 64.15,12.6 64.04,12.49 62.61,12.49 62.48,12.36 61.74,12.36 61.34,12.76 60.12,12.76 60.12,13.25 60.14,13.27
  region net D5: 56.25,13.27 56.11,13.13 56.11,12.41 56.12,12.4 57.16,12.4 57.53,12.77 58.62,12.77 58.62,13.23 58.58,13.27
  pour cut-out: 80.24,60.88 80.24,57.27 81.04,56.47 84.07,56.47 84.61,55.93 84.61,48.595 85.285,47.92 91.46,47.92 92.4,48.86 92.4,67.32 91.246,68.474 80.996,68.474 80.24,67.718
  region net 5V: 15.86,76.52 21.98,76.52 22.52,75.98 22.06,75.98 16.62,70.54 16.62,61.69 16.87,61.44 17.57,61.44 18.335,62.205 23.52,62.205 23.82,62.504 23.82,63.61 23.55,63.88 18.81,63.88 18.48,64.21 18.48,71.21 22.23,74.96 26.63,74.96 27.12,74.47 27.12,70.47 27.66,69.93 29.45,69.93 29.91,69.47 29.91,67.06 29.61,66.76 30.71,66.76 31.03,66.44 31.03,65.9 30.465,65.335 30.48,65.32 30.48,65.01 31.75,65.01 32.25,65.51 32.25,78.42 31.34,79.33 23.897,79.33 23.47,78.903 23.47,76.61 23.32,76.61 22.55,77.38 22.56,77.39 22.56,79.33 22.3,79.59 16.3,79.59 15.83,79.12 15.83,76.55
  region net NetL6_3: 13.7,67.67 14.3,68.27 14.3,76.1 13.86,76.54 10.88,76.54 10.86,76.56 10.86,79.32 11.11,79.57 14.66,79.57 15.36,78.87 15.36,65.54 15.28,65.46 13.75,65.46 13.7,65.51
  region net NetL6_4: 11.61,65.67 11.61,69.59 12.14,70.12 12.14,72.29 10.84,73.59 10.84,75.87 10.82,75.89 13.85,75.89 13.91,75.83 13.91,68.5 13.24,67.83 13.24,65.61 13.08,65.45 11.83,65.45
  region net GND1: 77.88,21.66 78.262,22.042 78.262,22.36 77.912,22.71 77.51,22.71 77.4,22.6 77.4,21.71 77.45,21.66
  region net GND1: 86.11,18.01 87.67,18.01 88.01,17.67 88.01,14.23 87.96,14.18 87.26,14.88 86.13,14.88 85.8,15.21 85.8,17.7
  region: 86.18,17.91
  region net GND1: 86.79,13.25 87.42,13.25 87.62,13.45 88.03,13.04 88.03,12.42 87.87,12.26 87.87,11.475 88.005,11.34 88.005,10.415 87.82,10.23 84.76,10.23 84.68,10.31 84.68,12.3 85.63,13.25
  region net VddOn: 84.296,41.19 84.296,39.694 84.4,39.59 84.877,39.59 84.97,39.683 84.97,41.19 84.94,41.22 84.33,41.22 84.3,41.19
  region net NetD2_1: 32.627,68.003 32.636,77.536 33.32,78.22 41.01,78.22 41.4,77.83 41.4,75.31 41.04,74.95 37.91,74.95 35.52,72.56 35.52,68.02 34.98,67.48 33.15,67.48
  region net NetR20_2: 24.14,68.02 24.37,68.25 29.4,68.25 29.54,68.11 29.54,67.64 29.41,67.51 25.85,67.51 25.34,67 25.34,65.56 25.26,65.48 24.42,65.48 24.14,65.76
  region net NetC10_1: 38.13,74.48 41.64,74.48 42.13,74.97 42.13,77.94 42.51,78.32 46.95,78.32 47.17,78.1 47.17,67.28 46.81,66.92 37.62,66.92 37.44,67.1 37.44,67.85 37.6,68.01 39.95,68.01 39.96,68 39.78,68 39.61,68.17 37.84,68.17 37.44,68.57 37.44,73.79
  region net NetC11_1: 47.58,77.78 47.58,67.34 48.1,66.82 57.16,66.82 60.63,70.29 60.63,70.91 52.3,70.91 50.88,69.49 50.88,68.18 50.74,68.18 50.74,69.67 52.27,71.2 52.27,78.03 51.98,78.32 48.12,78.32
  region net Vdd: 72.06,41.62 72.69,40.99 73.31,40.99 73.72,40.58 73.72,38.08 74.01,37.79 78.4,37.79 78.95,37.24 80.03,37.24 80.391,37.601 80.391,39.769 79.718,40.442 74.568,40.442 73.35,41.66 73.35,43.42 73.3,43.47 72.06,43.47
  region net NetQ15_1: 52.07,54.07 52.13,54.01 52.13,53.355 52.045,53.27 51.03,53.27 51.03,54.02 51.08,54.07
  region net NetNG1_1: 70.3,54.24 70.52,54.02 70.52,53.56 70.36,53.4 68.44,53.4 68.39,53.45 68.39,54.2 68.43,54.24
  region net GND2: 88.45,48.21 85.68,48.21 85.21,48.68 85.21,56.33 84.34,57.2 81.53,57.2 80.88,57.85 80.88,59.43 81.26,59.81 85.11,59.81 85.49,59.43 86.82,59.43 87.29,59.9 87.29,63.19 87.74,63.64 87.74,65.794 87.796,65.85 88.48,65.85 88.52,65.81 88.52,64.46 89.53,63.45 89.53,62.38 89.24,62.09 88.14,62.09 87.74,61.69 87.74,58.53 86.97,57.76 86.97,52.15 85.75,50.93 85.75,49.72 85.99,49.48 88.3,49.48 88.52,49.26 88.52,48.28
  region net 5V-b: 80.87,65.09 81.81,66.03 85.94,66.03 86.25,65.72 86.25,65.87 85.91,66.21 77.43,66.21 76.7,66.94 73.15,66.94 72.97,67.12 72.97,68.17 73.13,68.33 86.71,68.33 86.86,68.18 86.86,64.72 86.74,64.6 85.73,64.6 84.93,63.8 84.93,62.76 84.47,62.3 81.33,62.3 80.86,62.77 80.86,63.28 80.87,63.29
  region net NetQ15_3: 72.08,30.05 71.73,29.7 71.73,26.22 71.77,26.18 72.5,26.18 73.098,26.778 73.098,29.892 72.94,30.05
  region net NetQ10_3: 64.96,38.371 65.319,38.73 65.78,38.73 66,38.51 66,34.91 65.89,34.8 64.96,34.8
  region net NetQ10_1: 68.84,36.88 68.84,35.26 73.98,35.26 73.98,36.6 70.87,36.6 70.45,37.02 68.98,37.02
  region net NetQ10_3: 73.116,37.76 71.67,37.76 71.51,37.92 71.51,40.41 71.68,40.58 73.12,40.58 73.21,40.49 73.21,37.853
  region net Vdd-b: 84.22,37.63 84.22,35.67 84.26,35.63 84.96,35.63 84.97,35.64 84.97,37.62 84.99,37.64 84.23,37.64
  region net Vpp-b: 84.07,27.91 84.1,27.94 84.8,27.94 84.84,27.9 84.84,25.64 84.82,25.62 84.14,25.62 84.07,25.69
  region net AD-Vdd: 80.755,39.325 80.755,37.285 80.825,37.215 81.575,37.215 81.575,39.695 81.525,39.745 80.765,39.745 80.755,39.735
  region net NetC56_2: 23.45,61.61 24.16,62.32 24.16,63.76 24.29,63.89 26.66,63.89 26.9,63.65 26.9,61.2 26.22,60.52 22.67,60.52 22.66,60.53 22.66,61.61
  region net 12V: 64.95,45.57 64.95,46.21 65.46,46.72 70.18,46.72 70.45,46.45 70.45,45.38 70.33,45.26 65.29,45.26 64.97,45.58
  region net NetC31_1: 53.23,41.77 54.12,41.77 54.88,42.53 54.88,43.79 55.7,42.97 55.7,40.85 55.63,40.78 52.84,40.78 52.66,40.96 52.66,41.72 52.69,41.75 52.7,41.74 53.23,41.74
  region net NetJ4_2: 75.01,60.27 75.33,59.95 76.43,59.95 76.62,60.14 76.62,61.42 76.41,61.63 75.22,61.63 75.01,61.42
  region net NetR6_2: 14.351,59.907 11.289,62.986 11.289,64.701 11.569,64.981 13.239,64.981 13.299,64.921 13.299,63.001 14.351,61.948
  region net NetR7_2: 13.7,64.46 14.2,64.96 16.15,64.96 16.28,64.83 16.28,62.31 16.02,62.05 16.02,61.49 15.81,61.28 13.7,63.39
  pour cut-out: 74.364,35.31 74.366,34.23 73.94,34.23 73.92,34.21 73.92,35.18 74.06,35.32 74.354,35.32
  pour cut-out: 17.847,58.579 18.927,58.581 18.927,58.155 18.947,58.135 17.977,58.135 17.837,58.275 17.837,58.569
  pour cut-out: 19.516,53.435 19.514,54.535 19.96,54.535 19.96,53.565 19.82,53.425 19.526,53.425
  region net Vdd: 56.54,42.92 56.53,40.19 56.64,40.08 57.05,40.08 57.29,40.32 57.29,42.95 56.57,42.95
  region net Vpp: 51.02,52.69 51.8,52.69 51.81,52.68 51.81,50.59 51.77,50.55 51.03,50.55 51.02,50.56
  pour cut-out: 52.78,50.266 51.7,50.264 51.7,50.69 51.68,50.71 52.65,50.71 52.79,50.57 52.79,50.276
  region net Vdd-b: 93.66,37.44 93.86,37.24 93.86,36.26 93.52,35.92 89.87,35.92 89.87,37.42 89.89,37.44
  region net NetQ15_3: 71.23,26.24 66.46,26.24 64.88,24.66 64.88,22.5 64.95,22.43 67.46,22.43 67.67,22.64 67.67,24.59 68.19,25.11 71.89,25.11 72.7,25.92 72.7,27.1 72.095,27.105
  pour cut-out: 56.674,59.71 56.676,58.63 56.25,58.63 56.23,58.61 56.23,59.58 56.37,59.72 56.664,59.72
  pour cut-out: 62.434,59.65 62.436,58.57 62.01,58.57 61.99,58.55 61.99,59.52 62.13,59.66 62.424,59.66
  region net AD-VS-b: 58.53,58.61 60.56,58.61 60.57,58.6 60.57,57.64 60.44,57.51 58.39,57.51 58.28,57.62 58.28,58.55 58.34,58.61
  pour cut-out: 68.359,64.07 68.351,67.92 68.81,67.92 68.83,67.94 68.83,64.07
  region net NetQ15_1: 70.28,24.68 72.58,24.69 73.495,25.605 73.97,25.13 73.97,24.56 73.36,23.95 73.3,23.95 70.75,23.95 70.16,23.36 70.16,24.56
  region net NetQ4_2: 14.44,53.52 14.44,51.88 14.37,51.81 13.12,51.81 13.1,51.83 13.1,52.82 13.14,52.86 13.57,52.86 14.24,53.53 14.43,53.53
  pour cut-out: 40.72,52.296 39.62,52.294 39.62,52.74 40.59,52.74 40.73,52.6 40.73,52.306
  region net NetJ4_7: 86.99,60.25 86.99,63.65 87.37,64.03 87.37,64.53 87.31,64.59 87.14,64.59 86.8,64.25 85.985,64.25 85.445,63.71 85.445,60.285 85.93,59.8 86.54,59.8
  region net NetC60_2: 67.03,53.48 66.41,53.48 65.8,52.87 65.2,53.47 63.64,53.47 62.72,54.39 62.72,55.09 62.88,55.25 63.96,55.25 64.95,54.26 67.09,54.26 67.1,54.25 67.1,53.55
  pour cut-out: 66.338,57.736 65.258,57.734 65.258,58.16 65.238,58.18 66.208,58.18 66.348,58.04 66.348,57.746
  region net NetD2_1: 37,74.225 37,71.89 36.64,71.53 36.02,71.53 35.31,70.82 35.31,72.76 36.782,74.232
  pour cut-out: 19.496,51.569 19.494,52.669 19.94,52.669 19.94,51.699 19.8,51.559 19.506,51.559
  region net Vpp: 79.89,27.53 79.89,29.61 79.34,30.16 74.37,30.16 73.18,31.35 73.18,32.37 71.94,32.37 71.94,31.85 73.99,29.8 73.99,27.44 74.08,27.35 74.98,27.35 75.6,27.97 78.7,27.97 79.17,27.5 79.86,27.5
  region net NetBZ1_2: 52.28,28.11 52.28,27.65 52.45,27.48 52.98,27.48 53.18,27.68 53.18,27.93 53,28.11
  pour cut-out: 52.448,79.557 52.45,78.283 52.024,78.283 52.004,78.263 52.004,79.558
  region net 3.3V: 29.584,44.83 29.654,44.9 29.87,44.9 30.02,44.75 30.02,44.53 29.6,44.11 29.16,44.11 29.09,44.18 29.09,44.829
  region net AGND: 29.867,50 26.22,50 26.21,49.99 26.21,49.4 25.79,48.98 24.769,48.98 24.32,49.429 24.32,50 22.741,50 22.461,49.72 22.461,48.669 22.49,48.64 23.26,48.64 23.3,48.68 26.13,48.68 26.49,49.04 29.77,49.04 29.91,49.18 29.91,49.957

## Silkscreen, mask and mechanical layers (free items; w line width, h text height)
Top Overlay:
  drawing of 233 lines, arcs and shapes, not listed
  text "Vdd_b" at 80.89,35.99 h2
  text "VS_b" at 81.887,33.55 h2
  text "MISO_b" at 79.31,31.01 h2
  text "MOSI_b" at 79.31,28.39 h2
  text "CLK_b" at 80.622,25.93 h2
  text "Vpp_b" at 80.89,23.22 h2
  text "CSWrite3.0.1V0.51" at 37.296,21.71 h2
  text "GndContro1" at 98.64,21.07 h2 r90
  text "IO1_b" at 81.464,20.92 h2
  text "VR:0.51" at 43.963,18.97 h2
  text "Rest_b" at 80.436,18.21 h2
  text "2018/11/15" at 39.72,16.25 h2
  text "IO2_b" at 81.464,15.7 h2
  text "IO3_b" at 81.464,13.03 h2
Bottom Overlay:
  lines w0.2: 13.618,42.25 13.618,37.77 14.639,37.77
  text "3.3V" at 8.47,34.48 h2
  text "Boot0" at 8.41,32.22 h2
Top Solder:
  rectangle: 9.768,74.28 21.543,79.2
  rectangle: 80.87,0.84 90.6,4.88
  rectangle: 13.085,1.23 32.76,4.36
  rectangle: 34.3,1.28 41.14,9.39
  rectangle: 60.25,74.85 89.83,79.14
  rectangle: 87.544,41.58 98.98,47.6
  rectangle: 93.948,52.25 98.76,72.39
  rectangle: 2.23,8.19 9,17.05
  rectangle: 51.14,1.16 63.38,9.01
  rectangle: 26.61,74.42 52.09,78.98
  rectangle: 63.97,29.17 73.33,33.88
  rectangle: 65.35,42.481 75.37,46.2
  rectangle: 53.74,73.02 58.34,77.42
Bottom Solder:
  rectangle: 80.137,0.83 90.35,3.5
  rectangle: 16.656,5.206 19.8,7.35
  rectangle: 22.52,4.73 25.12,11.76
  rectangle: 20.57,15.77 24.595,18.33
  rectangle: 92.71,69.49 99.04,73.05
  rectangle: 67.65,74.59 85.65,77.66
